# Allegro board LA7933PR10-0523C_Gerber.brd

Outline 305.85 x 179.2 mm; copper layers: TOP, GND1, IN1, VCC, IN2, IN3, GND2, IN4, GND3, BOTTOM. Coordinates in mm from the lower left corner of the outline.

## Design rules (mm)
net group CLK_CPU_DMI: nets CLK_CPU_DMI CLK_CPU_DMI#
net group CLK_CPU_ITP: nets CLK_CPU_ITP CLK_CPU_ITP#
net group CLK_PCIE_CARD: nets CLK_PCIE_CARD CLK_PCIE_CARD#
net group CLK_PCIE_EXP: nets CLK_PCIE_EXP CLK_PCIE_EXP#
net group CLK_PCIE_LAN: nets CLK_PCIE_LAN CLK_PCIE_LAN#
net group CLK_PCIE_MINI1: nets CLK_PCIE_MINI1 CLK_PCIE_MINI1#
net group CLK_PCIE_MINI2: nets CLK_PCIE_MINI2 CLK_PCIE_MINI2#
net group CLK_PCIE_MINI3: nets CLK_PCIE_MINI3 CLK_PCIE_MINI3#
net group CLK_XDP: nets CLK_XDP CLK_XDP#
net group CLK_XDP_ITP: nets CLK_XDP_ITP CLK_XDP_ITP#
net group CRT-DDC: nets CLK_DDC2_CRT DAT_DDC2_CRT
net group CSS_1: nets CSSN_1 CSSP_1
net group DDR_A_0: nets DDR_A_DQS0 DDR_A_DQS#0
net group DDR_A_1: nets DDR_A_DQS1 DDR_A_DQS#1
net group DDR_A_2: nets DDR_A_DQS2 DDR_A_DQS#2
net group DDR_A_3: nets DDR_A_DQS3 DDR_A_DQS#3
net group DDR_A_4: nets DDR_A_DQS4 DDR_A_DQS#4
net group DDR_A_5: nets DDR_A_DQS5 DDR_A_DQS#5
net group DDR_A_6: nets DDR_A_DQS6 DDR_A_DQS#6
net group DDR_A_7: nets DDR_A_DQS7 DDR_A_DQS#7
net group DDR_B_0: nets DDR_B_DQS0 DDR_B_DQS#0
net group DDR_B_1: nets DDR_B_DQS1 DDR_B_DQS#1
net group DDR_B_2: nets DDR_B_DQS2 DDR_B_DQS#2
net group DDR_B_3: nets DDR_B_DQS3 DDR_B_DQS#3
net group DDR_B_4: nets DDR_B_DQS4 DDR_B_DQS#4
net group DDR_B_5: nets DDR_B_DQS5 DDR_B_DQS#5
net group DDR_B_6: nets DDR_B_DQS6 DDR_B_DQS#6
net group DDR_B_7: nets DDR_B_DQS7 DDR_B_DQS#7
net group DIFFPAIR0: nets CARD_SMBCLK CARD_SMBDAT
net group DIFFPAIR1: nets CHARGER_SMBCLK CHARGER_SMBDAT
net group DIFFPAIR2: nets DIMM2_SMBCLK DIMM2_SMBDAT
net group DIFFPAIR3: nets DIMM1_SMBCLK DIMM1_SMBDAT
net group DIFFPAIR4: nets DIMM3_SMBCLK DIMM3_SMBDAT
net group DIFFPAIR5: nets DIMM4_SMBCLK DIMM4_SMBDAT
net group DIFFPAIR6: nets DOCK_SMB_CLK DOCK_SMB_DAT
net group DIFFPAIR7: nets DDR_XDP_WAN_SMBCLK DDR_XDP_WAN_SMBDAT
net group DIFFPAIR10: nets GPU_SMBCLK GPU_SMBDAT
net group DIFFPAIR11: nets GPU_SMBCLK_R GPU_SMBDAT_R
net group DIFFPAIR12: nets HDMI_SCL_SINK HDMI_SDA_SINK
net group DIFFPAIR13: nets SML1_SMBCLK SML1_SMBDATA
net group DIFFPAIR14: nets MEM_SMBCLK MEM_SMBDATA
net group DIFFPAIR15: nets DDR_XDP_WAN_SMBCLK_R2 DDR_XDP_WAN_SMBDAT_R2
net group DIFFPAIR16: nets LAN_SMBCLK LAN_SMBDATA
net group DIFFPAIR17: nets LAN_SMBCLK_R LAN_SMBDATA_R
net group DIFFPAIR18: nets LCD_SMBCLK LCD_SMBDAT
net group DIFFPAIR19: nets MXM_CRT_DDC_CLK MXM_CRT_DDC_DAT
net group DIFFPAIR20: nets USH_SMBCLK USH_SMBDAT
net group DIFFPAIR21: nets BAY_SMBCLK BAY_SMBDAT
net group DIFFPAIR22: nets CLK_DDC2_DOCK DAT_DDC2_DOCK
net group DIFFPAIR23: nets PCH_CRT_DDC_CLK PCH_CRT_DDC_DAT
net group DIFFPAIR24: nets USBP1_R_D+ USBP1_R_D-
net group DIFFPAIR35: nets MXM_CURI2C_CLK MXM_CURI2C_DATA
net group DMI_CRX_PTX_0: nets DMI_CRX_PTX_N0 DMI_CRX_PTX_P0
net group DMI_CRX_PTX_1: nets DMI_CRX_PTX_N1 DMI_CRX_PTX_P1
net group DMI_CRX_PTX_2: nets DMI_CRX_PTX_N2 DMI_CRX_PTX_P2
net group DMI_CRX_PTX_3: nets DMI_CRX_PTX_N3 DMI_CRX_PTX_P3
net group DMI_CTX_PRX_0: nets DMI_CTX_PRX_N0 DMI_CTX_PRX_P0
net group DMI_CTX_PRX_1: nets DMI_CTX_PRX_N1 DMI_CTX_PRX_P1
net group DMI_CTX_PRX_2: nets DMI_CTX_PRX_N2 DMI_CTX_PRX_P2
net group DMI_CTX_PRX_3: nets DMI_CTX_PRX_N3 DMI_CTX_PRX_P3
net group DOCK_DCIN_IS: nets DOCK_DCIN_IS+ DOCK_DCIN_IS-
net group DOCK_LOM_TRD0: nets DOCK_LOM_TRD0+ DOCK_LOM_TRD0-
net group DOCK_LOM_TRD1: nets DOCK_LOM_TRD1+ DOCK_LOM_TRD1-
net group DOCK_LOM_TRD2: nets DOCK_LOM_TRD2+ DOCK_LOM_TRD2-
net group DOCK_LOM_TRD3: nets DOCK_LOM_TRD3+ DOCK_LOM_TRD3-
net group DPC_DOCK_AUX: nets DPC_DOCK_AUX DPC_DOCK_AUX#
net group DPC_DOCK_SW_AUX: nets DPC_DOCK_SW_AUX DPC_DOCK_SW_AUX#
net group DPD_DOCK_AUX: nets DPD_DOCK_AUX DPD_DOCK_AUX#
net group DPD_GPU_LANE_0: nets DPD_GPU_LANE_N0 DPD_GPU_LANE_P0
net group DPD_GPU_LANE_1: nets DPD_GPU_LANE_N1 DPD_GPU_LANE_P1
net group DPD_GPU_LANE_2: nets DPD_GPU_LANE_N2 DPD_GPU_LANE_P2
net group DPD_GPU_LANE_3: nets DPD_GPU_LANE_N3 DPD_GPU_LANE_P3
net group ESATA_PRX_DTX_4_C: nets ESATA_PRX_DTX_N4_C ESATA_PRX_DTX_P4_C
net group ESATA_PTX_DRX_4_C: nets ESATA_PTX_DRX_N4_C ESATA_PTX_DRX_P4_C
net group FDI_CTX_PRX_0: nets FDI_CTX_PRX_N0 FDI_CTX_PRX_P0
net group FDI_CTX_PRX_1: nets FDI_CTX_PRX_N1 FDI_CTX_PRX_P1
net group FDI_CTX_PRX_2: nets FDI_CTX_PRX_N2 FDI_CTX_PRX_P2
net group FDI_CTX_PRX_3: nets FDI_CTX_PRX_N3 FDI_CTX_PRX_P3
net group FDI_CTX_PRX_4: nets FDI_CTX_PRX_N4 FDI_CTX_PRX_P4
net group FDI_CTX_PRX_5: nets FDI_CTX_PRX_N5 FDI_CTX_PRX_P5
net group FDI_CTX_PRX_6: nets FDI_CTX_PRX_N6 FDI_CTX_PRX_P6
net group FDI_CTX_PRX_7: nets FDI_CTX_PRX_N7 FDI_CTX_PRX_P7
net group LAN_TX0: nets LAN_TX0+ LAN_TX0-
net group LAN_TX0R: nets LAN_TX0+R LAN_TX0-R
net group LAN_TX1: nets LAN_TX1+ LAN_TX1-
net group LAN_TX1R: nets LAN_TX1+R LAN_TX1-R
net group LAN_TX2: nets LAN_TX2+ LAN_TX2-
net group LAN_TX2R: nets LAN_TX2+R LAN_TX2-R
net group LAN_TX3: nets LAN_TX3+ LAN_TX3-
net group LAN_TX3R: nets LAN_TX3+R LAN_TX3-R
net group LCD_A0_PCH: nets LCD_A0+_PCH LCD_A0-_PCH
net group LCD_A1_PCH: nets LCD_A1+_PCH LCD_A1-_PCH
net group LCD_A2_PCH: nets LCD_A2+_PCH LCD_A2-_PCH
net group LCD_ACLK_PCH: nets LCD_ACLK+_PCH LCD_ACLK-_PCH
net group LCD_B0_PCH: nets LCD_B0+_PCH LCD_B0-_PCH
net group LCD_B1_PCH: nets LCD_B1+_PCH LCD_B1-_PCH
net group LCD_B2_PCH: nets LCD_B2+_PCH LCD_B2-_PCH
net group LCD_BCLK_PCH: nets LCD_BCLK+_PCH LCD_BCLK-_PCH
net group M_CLK_DDR0: nets M_CLK_DDR0 M_CLK_DDR#0
net group M_CLK_DDR1: nets M_CLK_DDR1 M_CLK_DDR#1
net group M_CLK_DDR2: nets M_CLK_DDR2 M_CLK_DDR#2
net group M_CLK_DDR3: nets M_CLK_DDR3 M_CLK_DDR#3
net group M_CLK_DDR4: nets M_CLK_DDR4 M_CLK_DDR#4
net group M_CLK_DDR5: nets M_CLK_DDR5 M_CLK_DDR#5
net group M_CLK_DDR6: nets M_CLK_DDR6 M_CLK_DDR#6
net group M_CLK_DDR7: nets M_CLK_DDR7 M_CLK_DDR#7
net group MB_DP_RP_0: nets MB_DP_RP_N0 MB_DP_RP_P0
net group MB_DP_RP_1: nets MB_DP_RP_N1 MB_DP_RP_P1
net group MB_DP_RP_2: nets MB_DP_RP_N2 MB_DP_RP_P2
net group MB_DP_RP_3: nets MB_DP_RP_N3 MB_DP_RP_P3
net group MB_DP_RP_AUX: nets MB_DP_RP_AUX MB_DP_RP_AUX#
net group MB_DP_RP_C_0: nets MB_DP_RP_C_N0 MB_DP_RP_C_P0
net group MB_DP_RP_C_1: nets MB_DP_RP_C_N1 MB_DP_RP_C_P1
net group MB_DP_RP_C_2: nets MB_DP_RP_C_N2 MB_DP_RP_C_P2
net group MB_DP_RP_C_3: nets MB_DP_RP_C_N3 MB_DP_RP_C_P3
net group MXM_DPB_0: nets MXM_DPB_N0 MXM_DPB_P0
net group MXM_DPB_1: nets MXM_DPB_N1 MXM_DPB_P1
net group MXM_DPB_3: nets MXM_DPB_N3 MXM_DPB_P3
net group MXM_DPB_AUX: nets MXM_DPB_AUX MXM_DPB_AUX#
net group MXM_DPC_0: nets MXM_DPC_N0 MXM_DPC_P0
net group MXM_DPC_0_C: nets MXM_DPC_N0_C MXM_DPC_P0_C
net group MXM_DPC_1: nets MXM_DPC_N1 MXM_DPC_P1
net group MXM_DPC_1_C: nets MXM_DPC_N1_C MXM_DPC_P1_C
net group MXM_DPC_2: nets MXM_DPC_N2 MXM_DPC_P2
net group MXM_DPC_2_C: nets MXM_DPC_N2_C MXM_DPC_P2_C
net group MXM_DPC_3: nets MXM_DPC_N3 MXM_DPC_P3
net group MXM_DPC_3_C: nets MXM_DPC_N3_C MXM_DPC_P3_C
net group MXM_DPC_AUX: nets MXM_DPC_AUX MXM_DPC_AUX#
net group MXM_DPC_AUX_C: nets MXM_DPC_AUX#_C MXM_DPC_AUX_C
net group MXM_LVDS_A0: nets MXM_LVDS_A0+ MXM_LVDS_A0-
net group MXM_LVDS_A1: nets MXM_LVDS_A1+ MXM_LVDS_A1-
net group MXM_LVDS_A2: nets MXM_LVDS_A2+ MXM_LVDS_A2-
net group MXM_LVDS_ACLK: nets MXM_LVDS_ACLK+ MXM_LVDS_ACLK-
net group MXM_LVDS_B0: nets MXM_LVDS_B0+ MXM_LVDS_B0-
net group MXM_LVDS_B1: nets MXM_LVDS_B1+ MXM_LVDS_B1-
net group MXM_LVDS_B2: nets MXM_LVDS_B2+ MXM_LVDS_B2-
net group MXM_LVDS_BCLK: nets MXM_LVDS_BCLK+ MXM_LVDS_BCLK-
net group MXM_MB_DP_0: nets MXM_MB_DP_N0 MXM_MB_DP_P0
net group MXM_MB_DP_0_C: nets MXM_MB_DP_N0_C MXM_MB_DP_P0_C
net group MXM_MB_DP_1: nets MXM_MB_DP_N1 MXM_MB_DP_P1
net group MXM_MB_DP_1_C: nets MXM_MB_DP_N1_C MXM_MB_DP_P1_C
net group MXM_MB_DP_2: nets MXM_MB_DP_N2 MXM_MB_DP_P2
net group MXM_MB_DP_2_C: nets MXM_MB_DP_N2_C MXM_MB_DP_P2_C
net group MXM_MB_DP_3: nets MXM_MB_DP_N3 MXM_MB_DP_P3
net group MXM_MB_DP_3_C: nets MXM_MB_DP_N3_C MXM_MB_DP_P3_C
net group MXM_MB_DP_AUX: nets MXM_MB_DP_AUX MXM_MB_DP_AUX#
net group MXM_MB_DP_AUX_C: nets MXM_MB_DP_AUX#_C MXM_MB_DP_AUX_C
net group NB_LAN_TX0: nets NB_LAN_TX0+ NB_LAN_TX0-
net group NB_LAN_TX2: nets NB_LAN_TX2+ NB_LAN_TX2-
net group NB_LAN_TX3: nets NB_LAN_TX3+ NB_LAN_TX3-
net group PCIE_CARD: nets PCIE_CARD PCIE_CARD#
net group PCIE_EXP: nets PCIE_EXP PCIE_EXP#
net group PCIE_LAN: nets PCIE_LAN PCIE_LAN#
net group PCIE_MINI1: nets PCIE_MINI1 PCIE_MINI1#
net group PCIE_MINI3: nets PCIE_MINI3 PCIE_MINI3#
net group PCIE_NVR: nets PCIE_NVR PCIE_NVR#
net group PCIE_SATA_PRX_NVRTX_6: nets PCIE_SATA_PRX_NVRTX_N6 PCIE_SATA_PRX_NVRTX_P6
net group PCIE_SATA_PTX_NVRRX_6: nets PCIE_SATA_PTX_NVRRX_N6 PCIE_SATA_PTX_NVRRX_P6
net group PEG_CRX_GTX_C_0: nets PEG_CRX_GTX_C_N0 PEG_CRX_GTX_C_P0
net group PEG_CRX_GTX_C_1: nets PEG_CRX_GTX_C_N1 PEG_CRX_GTX_C_P1
net group PEG_CRX_GTX_C_2: nets PEG_CRX_GTX_C_N2 PEG_CRX_GTX_C_P2
net group PEG_CRX_GTX_C_3: nets PEG_CRX_GTX_C_N3 PEG_CRX_GTX_C_P3
net group PEG_CRX_GTX_C_4: nets PEG_CRX_GTX_C_N4 PEG_CRX_GTX_C_P4
net group PEG_CRX_GTX_C_5: nets PEG_CRX_GTX_C_N5 PEG_CRX_GTX_C_P5
net group PEG_CRX_GTX_C_6: nets PEG_CRX_GTX_C_N6 PEG_CRX_GTX_C_P6
net group PEG_CRX_GTX_C_7: nets PEG_CRX_GTX_C_N7 PEG_CRX_GTX_C_P7
net group PEG_CRX_GTX_C_8: nets PEG_CRX_GTX_C_N8 PEG_CRX_GTX_C_P8
net group PEG_CRX_GTX_C_9: nets PEG_CRX_GTX_C_N9 PEG_CRX_GTX_C_P9
net group PEG_CRX_GTX_C_10: nets PEG_CRX_GTX_C_N10 PEG_CRX_GTX_C_P10
net group PEG_CRX_GTX_C_11: nets PEG_CRX_GTX_C_N11 PEG_CRX_GTX_C_P11
net group PEG_CRX_GTX_C_12: nets PEG_CRX_GTX_C_N12 PEG_CRX_GTX_C_P12
net group PEG_CRX_GTX_C_13: nets PEG_CRX_GTX_C_N13 PEG_CRX_GTX_C_P13
net group PEG_CRX_GTX_C_14: nets PEG_CRX_GTX_C_N14 PEG_CRX_GTX_C_P14
net group PEG_CRX_GTX_C_15: nets PEG_CRX_GTX_C_N15 PEG_CRX_GTX_C_P15
net group PEG_CTX_GRX_0: nets PEG_CTX_GRX_N0 PEG_CTX_GRX_P0
net group PEG_CTX_GRX_1: nets PEG_CTX_GRX_N1 PEG_CTX_GRX_P1
net group PEG_CTX_GRX_2: nets PEG_CTX_GRX_N2 PEG_CTX_GRX_P2
net group PEG_CTX_GRX_3: nets PEG_CTX_GRX_N3 PEG_CTX_GRX_P3
net group PEG_CTX_GRX_4: nets PEG_CTX_GRX_N4 PEG_CTX_GRX_P4
net group PEG_CTX_GRX_5: nets PEG_CTX_GRX_N5 PEG_CTX_GRX_P5
net group PEG_CTX_GRX_6: nets PEG_CTX_GRX_N6 PEG_CTX_GRX_P6
net group PEG_CTX_GRX_7: nets PEG_CTX_GRX_N7 PEG_CTX_GRX_P7
net group PEG_CTX_GRX_8: nets PEG_CTX_GRX_N8 PEG_CTX_GRX_P8
net group PEG_CTX_GRX_9: nets PEG_CTX_GRX_N9 PEG_CTX_GRX_P9
net group PEG_CTX_GRX_10: nets PEG_CTX_GRX_N10 PEG_CTX_GRX_P10
net group PEG_CTX_GRX_11: nets PEG_CTX_GRX_N11 PEG_CTX_GRX_P11
net group PEG_CTX_GRX_12: nets PEG_CTX_GRX_N12 PEG_CTX_GRX_P12
net group PEG_CTX_GRX_13: nets PEG_CTX_GRX_N13 PEG_CTX_GRX_P13
net group PEG_CTX_GRX_14: nets PEG_CTX_GRX_N14 PEG_CTX_GRX_P14
net group PEG_CTX_GRX_15: nets PEG_CTX_GRX_N15 PEG_CTX_GRX_P15
net group PSATA_PRX_DTX0_RP: nets PSATA_PRX_DTX_N0_RP PSATA_PRX_DTX_P0_RP
net group PSATA_PRX_DTX_0: nets PSATA_PRX_DTX_N0 PSATA_PRX_DTX_P0
net group PSATA_PRX_DTX_0_C: nets PSATA_PRX_DTX_N0_C PSATA_PRX_DTX_P0_C
net group PSATA_PTX_DRX0_RP: nets PSATA_PTX_DRX_N0_RP PSATA_PTX_DRX_P0_RP
net group PSATA_PTX_DRX_0: nets PSATA_PTX_DRX_N0 PSATA_PTX_DRX_P0
net group PSATA_PTX_DRX_0_C: nets PSATA_PTX_DRX_N0_C PSATA_PTX_DRX_P0_C
net group REM_DIODE1__4002: nets REM_DIODE1_N_4002 REM_DIODE1_P_4002
net group REM_DIODE2__4002: nets REM_DIODE2_N_4002 REM_DIODE2_P_4002
net group REM_DIODE3__4002: nets REM_DIODE3_N_4002 REM_DIODE3_P_4002
net group REM_DIODE4__4002: nets REM_DIODE4_N_4002 REM_DIODE4_P_4002
net group REM_DIODE5__4002: nets REM_DIODE5_N_4002 REM_DIODE5_P_4002
net group SATA_NVR_PRX_DTX_2: nets SATA_NVR_PRX_DTX_N2 SATA_NVR_PRX_DTX_P2
net group SATA_NVR_PTX_DRX_2: nets SATA_NVR_PTX_DRX_N2 SATA_NVR_PTX_DRX_P2
net group SATA_NVRAM_PRX_DTX_2_C: nets SATA_NVRAM_PRX_DTX_N2_C SATA_NVRAM_PRX_DTX_P2_C
net group SATA_NVRAM_PTX_DRX_2_C: nets SATA_NVRAM_PTX_DRX_N2_C SATA_NVRAM_PTX_DRX_P2_C
net group SATA_ODD_PRX_DTX_3: nets SATA_ODD_PRX_DTX_N3 SATA_ODD_PRX_DTX_P3
net group SATA_ODD_PRX_DTX_3_C: nets SATA_ODD_PRX_DTX_N3_C SATA_ODD_PRX_DTX_P3_C
net group SATA_ODD_PTX_DRX_3: nets SATA_ODD_PTX_DRX_N3 SATA_ODD_PTX_DRX_P3
net group SATA_ODD_PTX_DRX_3_C: nets SATA_ODD_PTX_DRX_N3_C SATA_ODD_PTX_DRX_P3_C
net group SATA_PRX_DKTX_5: nets SATA_PRX_DKTX_N5 SATA_PRX_DKTX_P5
net group SATA_PRX_DKTX_5_C: nets SATA_PRX_DKTX_N5_C SATA_PRX_DKTX_P5_C
net group SATA_PRX_DTX_0: nets SATA_PRX_DTX_N0 SATA_PRX_DTX_P0
net group SATA_PRX_DTX_1: nets SATA_PRX_DTX_N1 SATA_PRX_DTX_P1
net group SATA_PRX_DTX_1_C: nets SATA_PRX_DTX_N1_C SATA_PRX_DTX_P1_C
net group SATA_PRX_DTX_4: nets SATA_PRX_DTX_N4 SATA_PRX_DTX_P4
net group SATA_PTX_DKRX_5: nets SATA_PTX_DKRX_N5 SATA_PTX_DKRX_P5
net group SATA_PTX_DKRX_5_C: nets SATA_PTX_DKRX_N5_C SATA_PTX_DKRX_P5_C
net group SATA_PTX_DRX_0: nets SATA_PTX_DRX_N0 SATA_PTX_DRX_P0
net group SATA_PTX_DRX_1: nets SATA_PTX_DRX_N1 SATA_PTX_DRX_P1
net group SATA_PTX_DRX_1_C: nets SATA_PTX_DRX_N1_C SATA_PTX_DRX_P1_C
net group SATA_PTX_DRX_4: nets SATA_PTX_DRX_N4 SATA_PTX_DRX_P4
net group SW_LAN_TX0: nets SW_LAN_TX0+ SW_LAN_TX0-
net group SW_LAN_TX1: nets SW_LAN_TX1+ SW_LAN_TX1-
net group SW_LAN_TX2: nets SW_LAN_TX2+ SW_LAN_TX2-
net group SW_LAN_TX3: nets SW_LAN_TX3+ SW_LAN_TX3-
net group SW_LVDS_A0: nets SW_LVDS_A0+ SW_LVDS_A0-
net group SW_LVDS_A1: nets SW_LVDS_A1+ SW_LVDS_A1-
net group SW_LVDS_A2: nets SW_LVDS_A2+ SW_LVDS_A2-
net group SW_LVDS_ACLK: nets SW_LVDS_ACLK+ SW_LVDS_ACLK-
net group SW_LVDS_B0: nets SW_LVDS_B0+ SW_LVDS_B0-
net group SW_LVDS_B1: nets SW_LVDS_B1+ SW_LVDS_B1-
net group SW_LVDS_B2: nets SW_LVDS_B2+ SW_LVDS_B2-
net group SW_LVDS_BCLK: nets SW_LVDS_BCLK+ SW_LVDS_BCLK-
net group TMDSE_CON_: nets TMDSE_CON_CLK TMDSE_CON_CLK#
net group TMDSE_CON_0: nets TMDSE_CON_N0 TMDSE_CON_P0
net group TMDSE_CON_1: nets TMDSE_CON_N1 TMDSE_CON_P1
net group TMDSE_CON_2: nets TMDSE_CON_N2 TMDSE_CON_P2
net group TMDSE_RP_: nets TMDSE_RP_CLK TMDSE_RP_CLK#
net group TMDSE_RP_0: nets TMDSE_RP_N0 TMDSE_RP_P0
net group TMDSE_RP_1: nets TMDSE_RP_N1 TMDSE_RP_P1
net group TMDSE_RP_2: nets TMDSE_RP_N2 TMDSE_RP_P2
net group USB3_RX1_D: nets USB3_RX1_N_D- USB3_RX1_P_D+
net group USB3_RX2D-: nets USB3_RX2_N_D- USB3_RX2_P_D+
net group USB3_TX1_D: nets USB3_TX1_N_D- USB3_TX1_P_D+
net group USB3_TX2D-: nets USB3_TX2_N_D- USB3_TX2_P_D+
net group USB3R1: nets USB3RN1 USB3RP1
net group USB3R1_C: nets USB3RN1_C USB3RP1_C
net group USB3R1_RP: nets USB3RN1_RP USB3RP1_RP
net group USB3R1_RP_R: nets USB3RN1_RP_R USB3RP1_RP_R
net group USB3R2: nets USB3RN2 USB3RP2
net group USB3R2_C: nets USB3RN2_C USB3RP2_C
net group USB3R2_RP: nets USB3RN2_RP USB3RP2_RP
net group USB3R4: nets USB3RN4 USB3RP4
net group USB3T1: nets USB3TN1 USB3TP1
net group USB3T1_C: nets USB3TN1_C USB3TP1_C
net group USB3T1_RP: nets USB3TN1_RP USB3TP1_RP
net group USB3T1_RP_C: nets USB3TN1_RP_C USB3TP1_RP_C
net group USB3T2: nets USB3TN2 USB3TP2
net group USB3T2_C: nets USB3TN2_C USB3TP2_C
net group USB3T2_RP: nets USB3TN2_RP USB3TP2_RP
net group USB3T2_RP_C: nets USB3TN2_RP_C USB3TP2_RP_C
net group USB3T4: nets USB3TN4 USB3TP4
net group USB20: nets USBP1_D+ USBP1_D-
net group USB30: nets USB3RN2_RP_R USB3RP2_RP_R
net group USBP0: nets USBP0+ USBP0-
net group USBP0_D: nets USBP0_D+ USBP0_D-
net group USBP1: nets USBP1+ USBP1-
net group USBP2: nets USBP2+ USBP2-
net group USBP3: nets USBP3+ USBP3-
net group USBP4: nets USBP4+ USBP4-
net group USBP5: nets USBP5+ USBP5-
net group USBP6: nets USBP6+ USBP6-
net group USBP7: nets USBP7+ USBP7-
net group USBP8: nets USBP8+ USBP8-
net group USBP9: nets USBP9+ USBP9-
net group USBP9_D: nets USBP9_D+ USBP9_D-
net group USBP10: nets USBP10+ USBP10-
net group USBP11: nets USBP11+ USBP11-
net group USBP12: nets USBP12+ USBP12-
net group USBP12_D: nets USBP12_D+ USBP12_D-
net group USBP13: nets USBP13+ USBP13-
net group USBP13_D: nets USBP13_D+ USBP13_D-
net group VSUM: nets VSUM+ VSUM-
net group VSUMG: nets VSUMG+ VSUMG-
net group 10: nets MAX8731_IINP
net group AC97: nets PCH_AZ_BITCLK PCH_AZ_CODEC_BITCLK PCH_AZ_CODEC_RST# PCH_AZ_CODEC_SDIN0 PCH_AZ_CODEC_SDOUT PCH_AZ_CODEC_SYNC PCH_AZ_RST# PCH_AZ_SDOUT PCH_AZ_SYNC PCH_AZ_SYNC_Q SPKR
net group CLK: nets CLK_80H CLK_PCH_14M CLK_PCI_5048 CLK_PCI_DOCK CLK_PCI_LOOPBACK CLK_PCI_MEC CLK_PCI_TPM_TCM CLK_SIO_14M EC_32KHZ_ECE5048 JETWAY_14M JETWAY_CLK14M PCH_SPI_CLK PCI_5048 PCI_DOCK PCI_LOOPBACKOUT PCI_MEC PCI_TPM_TCM PCLK_80H SIO_14M SPI_CLK32 SPI_CLK64 SPI_PCH_CLK SUSCLK
net group COMP: nets DMI_COMP_R EDP_COMP PEG_COMP SATA3_COMP SATA_COMP SM_RCOMP0 SM_RCOMP1 SM_RCOMP2 XCLK_RCOMP
net group CPU: nets DDR3_DRAMRST# DDR3_DRAMRST#_CPU DDR3_DRAMRST#_R DDR_HVREF_RST DDR_HVREF_RST_GATE DDR_HVREF_RST_PCH H_CATERR# H_CPUPWRGD H_CPUPWRGD_R H_CPUPWRGD_XDP H_PM_SYNC H_PROCHOT# H_PROCHOT#_R H_THERMTRIP# H_THERMTRIP#_R PCH_JTAG_TCK PCH_JTAG_TMS PCH_PLTRST# PCH_PLTRST#_BUF PCH_PLTRST#_EC PCH_PLTRST#_R PLTRST_GPU# PLTRST_LAN# PLTRST_MMI# PLTRST_USH# PLTRST_XDP# PM_DRAM_PWRGD PM_DRAM_PWRGD_R PROCHOT#_EC RUNPWROK THERMATRIP2# VDDPWRGOOD XDP_RST#_R XDP_TCLK
net group CRT-DAC: nets BLUE_CRT BLUE_CRT_L BLUE_DOCK GREEN_CRT GREEN_CRT_L GREEN_DOCK MXM_CRT_BLU MXM_CRT_GRN MXM_CRT_RED PCH_CRT_BLU PCH_CRT_GRN PCH_CRT_RED RED_CRT RED_CRT_L RED_DOCK
net group CRT-SYNC: nets HSYNC_BUF HSYNC_DOCK HSYNC_L MXM_CRT_HSYNC MXM_CRT_VSYNC PCH_CRT_HSYNC PCH_CRT_VSYNC VSYNC_BUF VSYNC_DOCK VSYNC_L
net group CTL-LINK: nets PCH_CL_CLK1 PCH_CL_DATA1 PCH_CL_RST1#
net group DDRA-CMD: nets DDR_A_BS0 DDR_A_BS1 DDR_A_BS2 DDR_A_CAS# DDR_A_MA0 DDR_A_MA1 DDR_A_MA2 DDR_A_MA3 DDR_A_MA4 DDR_A_MA5 DDR_A_MA6 DDR_A_MA7 DDR_A_MA8 DDR_A_MA9 DDR_A_MA10 DDR_A_MA11 DDR_A_MA12 DDR_A_MA13 DDR_A_MA14 DDR_A_MA15 DDR_A_RAS# DDR_A_WE#
net group DDRA-CTL: nets DDR_CKE0_DIMM2 DDR_CKE1_DIMM2 DDR_CKE4_DIMM1 DDR_CKE5_DIMM1 DDR_CS0_DIMM2# DDR_CS1_DIMM2# DDR_CS4_DIMM1# DDR_CS5_DIMM1# M_ODT0 M_ODT1 M_ODT4 M_ODT5
net group DDRA-D0: nets DDR_A_D0 DDR_A_D1 DDR_A_D2 DDR_A_D3 DDR_A_D4 DDR_A_D5 DDR_A_D6 DDR_A_D7
net group DDRA-D1: nets DDR_A_D8 DDR_A_D9 DDR_A_D10 DDR_A_D11 DDR_A_D12 DDR_A_D13 DDR_A_D14 DDR_A_D15
net group DDRA-D2: nets DDR_A_D16 DDR_A_D17 DDR_A_D18 DDR_A_D19 DDR_A_D20 DDR_A_D21 DDR_A_D22 DDR_A_D23
net group DDRA-D3: nets DDR_A_D24 DDR_A_D25 DDR_A_D26 DDR_A_D27 DDR_A_D28 DDR_A_D29 DDR_A_D30 DDR_A_D31
net group DDRA-D4: nets DDR_A_D32 DDR_A_D33 DDR_A_D34 DDR_A_D35 DDR_A_D36 DDR_A_D37 DDR_A_D38 DDR_A_D39
net group DDRA-D5: nets DDR_A_D40 DDR_A_D41 DDR_A_D42 DDR_A_D43 DDR_A_D44 DDR_A_D45 DDR_A_D46 DDR_A_D47
net group DDRA-D6: nets DDR_A_D48 DDR_A_D49 DDR_A_D50 DDR_A_D51 DDR_A_D52 DDR_A_D53 DDR_A_D54 DDR_A_D55
net group DDRA-D7: nets DDR_A_D56 DDR_A_D57 DDR_A_D58 DDR_A_D59 DDR_A_D60 DDR_A_D61 DDR_A_D62 DDR_A_D63
net group DDRB-CMD: nets DDR_B_BS0 DDR_B_BS1 DDR_B_BS2 DDR_B_CAS# DDR_B_MA0 DDR_B_MA1 DDR_B_MA2 DDR_B_MA3 DDR_B_MA4 DDR_B_MA5 DDR_B_MA6 DDR_B_MA7 DDR_B_MA8 DDR_B_MA9 DDR_B_MA10 DDR_B_MA11 DDR_B_MA12 DDR_B_MA13 DDR_B_MA14 DDR_B_MA15 DDR_B_RAS# DDR_B_WE#
net group DDRB-CTL: nets DDR_CKE2_DIMM4 DDR_CKE3_DIMM4 DDR_CKE6_DIMM3 DDR_CKE7_DIMM3 DDR_CS2_DIMM4# DDR_CS3_DIMM4# DDR_CS6_DIMM3# DDR_CS7_DIMM3# M_ODT2 M_ODT3 M_ODT6 M_ODT7
net group DDRB-D0: nets DDR_B_D0 DDR_B_D1 DDR_B_D2 DDR_B_D3 DDR_B_D4 DDR_B_D5 DDR_B_D6 DDR_B_D7
net group DDRB-D1: nets DDR_B_D8 DDR_B_D9 DDR_B_D10 DDR_B_D11 DDR_B_D12 DDR_B_D13 DDR_B_D14 DDR_B_D15
net group DDRB-D2: nets DDR_B_D16 DDR_B_D17 DDR_B_D18 DDR_B_D19 DDR_B_D20 DDR_B_D21 DDR_B_D22 DDR_B_D23
net group DDRB-D3: nets DDR_B_D24 DDR_B_D25 DDR_B_D26 DDR_B_D27 DDR_B_D28 DDR_B_D29 DDR_B_D30 DDR_B_D31
net group DDRB-D4: nets DDR_B_D32 DDR_B_D33 DDR_B_D34 DDR_B_D35 DDR_B_D36 DDR_B_D37 DDR_B_D38 DDR_B_D39
net group DDRB-D5: nets DDR_B_D40 DDR_B_D41 DDR_B_D42 DDR_B_D43 DDR_B_D44 DDR_B_D45 DDR_B_D46 DDR_B_D47
net group DDRB-D6: nets DDR_B_D48 DDR_B_D49 DDR_B_D50 DDR_B_D51 DDR_B_D52 DDR_B_D53 DDR_B_D54 DDR_B_D55
net group DDRB-D7: nets DDR_B_D56 DDR_B_D57 DDR_B_D58 DDR_B_D59 DDR_B_D60 DDR_B_D61 DDR_B_D62 DDR_B_D63
net group DP: nets DPC_DOCK_LANE_C_N0 DPC_DOCK_LANE_C_N1 DPC_DOCK_LANE_C_N2 DPC_DOCK_LANE_C_N3 DPC_DOCK_LANE_C_P0 DPC_DOCK_LANE_C_P1 DPC_DOCK_LANE_C_P2 DPC_DOCK_LANE_C_P3 DPC_DOCK_LANE_N0_R DPC_DOCK_LANE_N1_R DPC_DOCK_LANE_N2_R DPC_DOCK_LANE_N3_R DPC_DOCK_LANE_P0_R DPC_DOCK_LANE_P1_R DPC_DOCK_LANE_P2_R DPC_DOCK_LANE_P3_R DPD_DOCK_LANE_N0 DPD_DOCK_LANE_N0_R DPD_DOCK_LANE_N1 DPD_DOCK_LANE_N1_R DPD_DOCK_LANE_N2 DPD_DOCK_LANE_N2_R DPD_DOCK_LANE_N3 DPD_DOCK_LANE_N3_R DPD_DOCK_LANE_P0 DPD_DOCK_LANE_P0_R DPD_DOCK_LANE_P1 DPD_DOCK_LANE_P1_R DPD_DOCK_LANE_P2 DPD_DOCK_LANE_P2_R DPD_DOCK_LANE_P3 DPD_DOCK_LANE_P3_R MXM_DPB_N2 MXM_DPB_P2 MXM_DPC_HPD MXM_EDP_HPD MXM_MB_DP_HPD
net group EDP: nets MXM_EDP_AUX+ MXM_EDP_AUX+_C MXM_EDP_AUX- MXM_EDP_AUX-_C MXM_EDP_TX0+ MXM_EDP_TX0+_C MXM_EDP_TX0- MXM_EDP_TX0-_C MXM_EDP_TX1+ MXM_EDP_TX1+_C MXM_EDP_TX1- MXM_EDP_TX1-_C MXM_EDP_TX2+ MXM_EDP_TX2+_C MXM_EDP_TX2- MXM_EDP_TX2-_C MXM_EDP_TX3+ MXM_EDP_TX3+_C MXM_EDP_TX3- MXM_EDP_TX3-_C
net group FDI-CTL: nets FDI_FSYNC0 FDI_FSYNC1 FDI_INT FDI_LSYNC0 FDI_LSYNC1
net group GND: nets GND
net group HOSTCLK: nets CLK_BCLK_ITP CLK_BCLK_ITP# CLK_BUF_BCLK CLK_BUF_CKSSCD CLK_BUF_CKSSCD# CLK_BUF_DMI CLK_BUF_DMI# CLK_BUF_DOT96 CLK_BUF_DOT96# CLK_PCIE_VGA CLK_PCIE_VGA# CPU_DMI CPU_DMI# CPU_DPLL CPU_DPLL#
net group LAN: nets NB_LAN_TX0+_R NB_LAN_TX0-_R NB_LAN_TX1+ NB_LAN_TX1+_R NB_LAN_TX1- NB_LAN_TX1-_R
net group LVDS-CTL: nets LDDC_CLK_PCH LDDC_CLK_SW LDDC_DATA_PCH LDDC_DATA_SW MXM_LVDS_DDC_CLK MXM_LVDS_DDC_DAT
net group PCIE: nets PCIE_PRX_EXPTX_N3 PCIE_PRX_EXPTX_P3 PCIE_PRX_GLANTX_N7 PCIE_PRX_GLANTX_N7_C PCIE_PRX_GLANTX_P7 PCIE_PRX_GLANTX_P7_C PCIE_PRX_MMITX_N8 PCIE_PRX_MMITX_P8 PCIE_PRX_NVRTX_N6 PCIE_PRX_NVRTX_P6 PCIE_PRX_WANTX_N1 PCIE_PRX_WANTX_P1 PCIE_PRX_WLANTX_N2 PCIE_PRX_WLANTX_P2 PCIE_PRX_WPANTX_N5 PCIE_PRX_WPANTX_P5 PCIE_PTX_EXPRX_N3 PCIE_PTX_EXPRX_P3 PCIE_PTX_GLANRX_N7 PCIE_PTX_GLANRX_N7_C PCIE_PTX_GLANRX_P7 PCIE_PTX_GLANRX_P7_C PCIE_PTX_MMIRX_N8 PCIE_PTX_MMIRX_P8 PCIE_PTX_NVRRX_N6 PCIE_PTX_NVRRX_N6_C PCIE_PTX_NVRRX_P6 PCIE_PTX_NVRRX_P6_C PCIE_PTX_WANRX_N1 PCIE_PTX_WANRX_N1_C PCIE_PTX_WANRX_P1 PCIE_PTX_WANRX_P1_C PCIE_PTX_WLANRX_N2 PCIE_PTX_WLANRX_N2_C PCIE_PTX_WLANRX_P2 PCIE_PTX_WLANRX_P2_C PCIE_PTX_WPANRX_N5 PCIE_PTX_WPANRX_N5_C PCIE_PTX_WPANRX_P5 PCIE_PTX_WPANRX_P5_C
net group PEG: nets PEG_CRX_GTX_N1 PEG_CRX_GTX_N2 PEG_CRX_GTX_N3 PEG_CRX_GTX_N4 PEG_CRX_GTX_N5 PEG_CRX_GTX_N6 PEG_CRX_GTX_N7 PEG_CRX_GTX_N9 PEG_CRX_GTX_N10 PEG_CRX_GTX_N13 PEG_CRX_GTX_N15 PEG_CRX_GTX_P0 PEG_CRX_GTX_P1 PEG_CRX_GTX_P2 PEG_CRX_GTX_P3 PEG_CRX_GTX_P4 PEG_CRX_GTX_P5 PEG_CRX_GTX_P6 PEG_CRX_GTX_P7 PEG_CRX_GTX_P8 PEG_CRX_GTX_P9 PEG_CRX_GTX_P10 PEG_CRX_GTX_P11 PEG_CRX_GTX_P12 PEG_CRX_GTX_P13 PEG_CRX_GTX_P14 PEG_CRX_GTX_P15 PEG_CTX_GRX_C_N0 PEG_CTX_GRX_C_N1 PEG_CTX_GRX_C_N2 PEG_CTX_GRX_C_N3 PEG_CTX_GRX_C_N4 PEG_CTX_GRX_C_N5 PEG_CTX_GRX_C_N6 PEG_CTX_GRX_C_N7 PEG_CTX_GRX_C_N8 PEG_CTX_GRX_C_N9 PEG_CTX_GRX_C_N10 PEG_CTX_GRX_C_N11 PEG_CTX_GRX_C_N12 PEG_CTX_GRX_C_N13 PEG_CTX_GRX_C_N14 PEG_CTX_GRX_C_N15 PEG_CTX_GRX_C_P0 PEG_CTX_GRX_C_P1 PEG_CTX_GRX_C_P2 PEG_CTX_GRX_C_P3 PEG_CTX_GRX_C_P4 PEG_CTX_GRX_C_P5 PEG_CTX_GRX_C_P6 PEG_CTX_GRX_C_P7 PEG_CTX_GRX_C_P8 PEG_CTX_GRX_C_P9 PEG_CTX_GRX_C_P10 PEG_CTX_GRX_C_P11 PEG_CTX_GRX_C_P12 PEG_CTX_GRX_C_P13 PEG_CTX_GRX_C_P14 PEG_CTX_GRX_C_P15
net group PEG_CRX_GTX_0: nets PEG_CRX_GTX_N0
net group PEG_CRX_GTX_8: nets PEG_CRX_GTX_N8
net group PEG_CRX_GTX_11: nets PEG_CRX_GTX_N11
net group PEG_CRX_GTX_12: nets PEG_CRX_GTX_N12
net group PEG_CRX_GTX_14: nets PEG_CRX_GTX_N14
net group RTC: nets PCH_RTCRST# PCH_RTCX1 PCH_RTCX2 PCH_RTCX2_R SRTCRST#
net group SENSE: nets VAXG_VAL_SENSE VCC_AXG_SENSE VCCSENSE VCCSENSE_R VSS_AXG_SENSE VSSAXG_VAL_SENSE VSSSENSE VSSSENSE_R
net group SMB: nets PBAT_SMBCLK PBAT_SMBDAT WWAN_SMBCLK WWAN_SMBDAT
net group SPI: nets SPI_DIN32 SPI_DIN64 SPI_DO32 SPI_DO64 SPI_HOLD# SPI_PCH_CS0# SPI_PCH_CS0#_R SPI_PCH_CS1# SPI_PCH_CS1#_R SPI_PCH_DIN SPI_PCH_DO SPI_WP#_SEL SPI_WP#_SEL_R
net group SRCCLK: nets CLK_PCIE_NVR CLK_PCIE_NVR# PCIE_MINI2 PCIE_MINI2#
net group SVID: nets H_CPU_SVIDALRT# PECI_EC PECI_EC_R VCCSA_VID_0 VCCSA_VID_1 VIDALERT_N VIDSCLK VIDSOUT
net group UIM: nets UIM_CLK UIM_DATA UIM_RESET UIM_VPP
net group XDP: nets XDP_DBRESET# XDP_DBRESET#_R XDP_FN0 XDP_FN1 XDP_FN2 XDP_FN3 XDP_FN4 XDP_FN5 XDP_FN6 XDP_FN7 XDP_FN8 XDP_FN9 XDP_FN10 XDP_FN11 XDP_FN12 XDP_FN13 XDP_FN14 XDP_FN15 XDP_FN16 XDP_FN17 XDP_HOOK2 XDP_OBS0_R XDP_OBS1_R XDP_OBS2_R XDP_OBS3_R XDP_OBS4_R XDP_OBS5_R XDP_OBS6_R XDP_OBS7_R XDP_PRDY# XDP_PREQ# XDP_TDI XDP_TDI_R XDP_TDO XDP_TDO_R XDP_TMS XDP_TRST#
nets with their own width: min track width 0.127; nets +5V_HDMI_DDC
nets with their own width: min track width 0.203; nets MEC_XTAL1 MEC_XTAL2 MEC_XTAL2_R XTALI XTALO XTALO_R
nets with their own width: min track width 0.254; nets 1.05V_A_PWRGD 1.5V_B+ 1.5V_RUN_PWRGD 1.5V_SUS_PWRGD 1.05V_VTTPWRGD 1.5VSP_FB 1.8V_RUN_PWRGD 1.8VSP_FB 2VREF_6182 3301_ACAV_IN_NB 3301_DC_IN_SS 3301_PWRSRC +1.05V_M_VCCSUS +1.5V_RUNP +CHGR_DC_IN +VCC_GFXCORE +VCCSA_EN +VCCSA_PWRGD +VCHGR ACAV_DOCK_SRC# ACAV_IN ACAVDK_SRC ACAVIN ALW_PWRGD_3V_5V BLK_MOSFET_GC CD3301_SDC_IN CD_PBATT_OFF CPU_VTT_ON CS_1.5V CSS_GC DC_BLOCK_GC DDR_1.5V_CNTRL0 DDR_1.5V_CNTRL1 DK_AC_OFF DK_AC_OFF_EN DK_CSS_GC DK_PWR_BAR DSCHRG_MOSFET_GC EN_1.5VSP EN_1.8VSP EN_+V1.05S_VCCPP EN_+V1.05SP EN_DK_PWRBAR EN_DOCK_PWR_BAR ENTRIP1 ENTRIP2 ERC2 FB_3V FB_5V FB_+V1.05S_VCCPP FB_+V1.05SP GP1_SW GP2_SW ICOUT MAX8731_REF MOD_EN N17083694 N17319754 N21585007 N21631518 N21750145 N21752779 N22506578 N27995579 N27996731 N28024997 N28058271 N32893408 N32893413 N41278453 N41278459 N41278463 N41278649 N41343073 N47460076 N47645618 N47645638 N47645648 N47912959 N47913307 N47935277 N47935283 N47935329 N47935331 N47935380 N47935394 N47935396 N47935402 N47935438 N47935442 N47935444 N47935488 N47935534 N47935814 N47935824 N47935848 N47935871 N85751867 N85751946 N141046431 NTCG P1_SW P2_SW P3_SW P33ALW P33ALW2 P50ALW PWM3 REGCTL_PNP10 RF_+V1.05S_VCCPP RF_+V1.05SP RUN_GFX_ON RUN_GFX_ON# RUN_ON_CPU1.5VS3 S3_1.5V S5_1.5V SL_BAT_PRES# STSTART_DCBLOCK_GC TRIP_+V1.05S_VCCPP TRIP_+V1.05SP VCCP_PWRCTRL VCCSA_SENSE VCCSAPWROK VFB VSS_NCTF_1 VSS_NCTF_2 VSS_NCTF_3 VSS_NCTF_4 VSS_NCTF_5 VSS_NCTF_6 VSS_NCTF_7 VSS_NCTF_8 VSS_NCTF_9 VSS_NCTF_10 VSS_NCTF_11 VSS_NCTF_12 VSS_NCTF_13 VSS_NCTF_14 VSS_NCTF_15 VSS_NCTF_16 VSS_NCTF_17 VSS_NCTF_18 VSS_NCTF_19 VSS_NCTF_20 VSS_NCTF_21 VSS_NCTF_22 VSS_NCTF_23 VSS_NCTF_24 VSS_NCTF_25 VSS_NCTF_26 VSS_NCTF_27 VSS_NCTF_28 VSS_NCTF_29 VSS_NCTF_30 VSS_NCTF_31 VSS_NCTF_32 Z4304 Z4305 Z4306
nets with their own width: min track width 0.305; nets FFS_INT2 FFS_INT2_Q HDD_FALL_INT
nets with their own width: min track width 0.381; nets N17708032 N17708061 SOFT_START_GC
nets with their own width: min track width 0.508; nets +1.0V_LAN +1.5V_CPU_VDDQ +1.05V_M +1.5V_MEM +1.05V_RUN +1.5V_RUN +1.5V_RUN_CHG +1.05V_RUN_ENABLE +1.05V_RUN_VCCA_A_DPL +1.05V_RUN_VCCA_B_DPL +1.05V_RUN_VCCCLKDMI +1.05V_RUN_VTT +1.05VTTP +3.3V_ALW +3.3V_ALW2 +3.3V_ALW_PCH +3.3V_ALW_PCH_JTAG +3.3V_ALW_U46 +3.3V_ALWP +3.3V_ALWPCH_CHG +3.3V_LAN_OUT +3.3V_M +3.3V_M_CHG +3.3V_MXM +3.3V_RTC_LDO +3.3V_RUN +3.3V_RUN_CHG +3.3V_RUN_ENABLE +3.3V_RUN_VCC_CLKF33 +3.3V_SB3V +3.3V_SPI +3.3V_SUS +3.3V_SUS_CHG +3V_ALW_PCH_ENABLE +3VM_THRM +3VMXM_D +3VMXM_GATE +5V_ALW +5V_ALW2 +5V_ALW_ESATA +5V_ALW_PCH +5V_ALWP +5V_RUN +5V_RUN_CHG +5V_RUN_ENABLE +5VMXM_D +5VMXM_GATE +A_ENABLE +COINCELL +DC_IN +DC_IN_SS +DCIN +DDR_CHG +DIMM0_1_CA_CPU +DIMM0_1_VREF_CPU +DIMM1_VREF_DQ +DIMM3_VREF_DQ +DIMM4_VREF_CA +DIMM4_VREF_DQ +DOCK_PWR_BAR +ENAB_3VLAN +MXM_PWR_SRC +NBDOCK_DC_IN_SS +PCH_V5REF_RUN +PCH_V5REF_SUS +PECI_VREF +PWR_SRC_S +RTC_CELL +RTC_CELL_VBAT +SDC_IN +SIM_PWR +TRM_CT1 +TRM_CT2 +TRM_CT3 +TRM_CT4 +USB1_REPEATER_VDD +USB2_REPEATER_VDD +V_DDR_REF +V_DDR_REFA_M3 +V_DDR_REFB_M3 +V_DDR_SMREF +V_SM_VREF_CNT +VCC_CORE +VCC_SA +VCCACLK +VCCADAC +VCCAFDI_VRM +VCCAPLL_CPY_PCH +VCCAPLL_FDI +VCCAPLLEXP +VCCDSW3_3 +VCCSA_BT +VCCSA_BT_1 +VCCSA_P +VCCSA_SNUB +VCCSATAPLL +VCCSPI BLKNG_MOSFET_GC BOOT BOOT_1.5V BOOT_D BST_5V BST_+V1.05S_VCCPP CD3301_DCIN CHG_SNUB ERC1 ERC3 GND_CHASSIS GNDA_CHG GNDA_VCCSA MAX8731A_LDO N17684555 N21631508 N27967271 N32934056 N47912533 N47935337 N85751870 N141046260 PBATT+ SNUB_1.5V SNUB_1.5VSP SNUB_1.8VSP SNUB_+V1.05S_VCCPP SW_1.5V VDD_1.5V Z4012
nets with their own width: min track width 0.635; nets BOOT1 BOOT1G BOOT2 BOOT2G BOOT3 BST1_3V BST1_5V BST_3V PHASE2G PHASE3 SNUB_3V SNUB_5V SW_+V1.05SP UG_+V1.05SP UGATE2G UGATE3
nets with their own width: min track width 0.762; nets 1.5VSP_VIN +1.8V_RUN_LVDS +VCHGR_B CHG_LGATE CHG_UGATE LG_+V1.05S_VCCPP LG_+V1.05SP LX_5V SW_+V1.05S_VCCPP UG_5V UG_+V1.05S_VCCPP
nets with their own width: min track width 1.016; nets +0.75VSP +1.5VP +3.3V_LAN +3.3V_PCIE_NVM +3.3V_RUN_TPM +5V_RUN_CRT +5V_RUN_HDMI +CAMERA_VDD +CRT_VCC +DP_VCC +VCCDFTERM +VDISPLAY_VCC DH_1.5V DL_1.5V LG_3V LG_5V LGATE1 LGATE1G LGATE2 LGATE2G LGATE3 LX_3V PHASE2 UG_3V UGATE1 UGATE1G UGATE2
nets with their own width: min track width 2.032; nets +0.75V_DDR_VTT +1.8V_RUN +3.3V_PCIE_FLASH +3.3V_WLAN +5V_HDD +5V_USB_PWR1 +5V_USB_PWR2 +BL_PWR_SRC +DIMM2_VREF_DQ +EDPVDD +LCDVDD +PWR_SRC
nets with their own width: min track width 2.54; nets +5V_ESATA_PWR +5V_MXM
nets with their own width: min track width 3.048; nets +3.3V_PCIE_WWAN
nets with their own width: min track width 4.064; nets +5V_MOD

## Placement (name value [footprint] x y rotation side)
C1  -  [C_0603]  208.14 173.18 90 top
C2  -  [C_1206]  209.59 173.29 0 top
C3  -  [C_0603]  210.11 175.34 0 top
C4  -  [C_0402]  209.01 175.67 180 top
C7  -  [C_0402]  193.62 162.37 180 top
C8  -  [C_0402]  208.16 91.5 0 top
C12  -  [C_0402]  52.71 164.3 0 top
C13  -  [C_0402]  55.69 164.3 180 top
C14  -  [C_0402]  66.94 169.48 0 top
C15  -  [C_0402]  67.66 167.92 270 top
C18  -  [C_0402]  68.97 169.48 0 top
C19  -  [C_0402]  65.6 169.48 180 top
C20  -  [C_0402]  48.36 159.03 270 bottom
C21  -  [C_0402]  48.95 164.26 0 top
C22  -  [C_0402]  55.22 159.03 270 bottom
C23  -  [C_0402]  52.17 159.03 270 bottom
C24  -  [C_0402]  216.73 85.15 180 bottom
C45  -  [C_0402]  166.98 95.53 270 top
C48  -  [C_0402]  167.99 95.53 270 top
C52  -  [C_0402]  115.9 31.23 180 top
C53  -  [C_0402]  122.78 31.59 90 top
C56  -  [C_0402]  122.78 28.48 270 top
C86  -  [C_0402]  46.7 143.9 180 bottom
C87  -  [C_0402]  277.94 68.52 180 bottom
C88  -  [C_0402]  289.82 70.17 0 bottom
C90  -  [C_0402]  211.81 132.81 90 top
C91  -  [C_0402]  212.53 156.08 270 top
C92  -  [C_0402]  201.49 153.25 180 bottom
C93  -  [C_0402]  43.18 164.86 180 top
C94  -  [C_0402]  198.9 85.85 0 top
C95  -  [C_0402]  209.44 112.47 180 bottom
C96  -  [C_0402]  214.22 106.2 270 bottom
C242  -  [C_0402]  48.9 144.08 0 top
C243  -  [C_0402]  75.96 140.23 270 top
C244  -  [C_0402]  61.05 152.66 90 top
C245  -  [C_0402]  48.9 148.15 0 top
C246  -  [C_0402]  48.9 149.16 0 top
C247  -  [C_0402]  48.9 143.07 0 top
C248  -  [C_0402]  80.62 129.32 270 top
C249  -  [C_0603]  79.35 138.8 90 top
C250  -  [C_0603]  63.71 152.34 180 top
C251  -  [C_0402]  48.9 146.11 0 top
C252  -  [C_0402]  48.9 145.1 0 top
C253  -  [C_0402]  48.93 142.02 0 top
C254  -  [C_0402]  48.9 147.13 0 top
C255  -  [C_0402]  71.98 162.84 270 bottom
C256  -  [C_0402]  69.58 153.45 270 top
C257  -  [C_0402]  164.37 98.98 270 top
C258  -  [C_0402]  149.49 108.78 0 top
C259  -  [C_0402]  143.07 109.03 180 top
C260  -  [C_0603]  33.83 14.03 180 bottom
C272  -  [C_0402]  133.3 130.87 180 bottom
C279  -  [C_0402]  281.28 67.53 90 bottom
C280  -  [C_0402]  285.34 67.53 90 bottom
C281  -  [C_0402]  283.31 67.53 90 bottom
C282  -  [C_0402]  280.26 67.53 90 bottom
C283  -  [C_0402]  284.33 67.53 90 bottom
C284  -  [C_0402]  288.39 67.53 90 bottom
C285  -  [C_0402]  289.41 67.53 90 bottom
C286  -  [C_0402]  282.29 67.53 90 bottom
C287  -  [C_0402]  145.13 167.99 90 top
C288  -  [C_0402]  123.32 63.06 0 bottom
C289  -  [C_0402]  181.68 149.92 180 bottom
C290  -  [C_0402]  183.96 145.61 180 bottom
C292  -  [C_0402]  71.22 145.64 90 bottom
C293  -  [C_0402]  74.52 150.21 90 bottom
C294  -  [C_0402]  169.3 58.23 0 bottom
C295  -  [C_0402]  284.07 81.06 270 bottom
C296  -  [C_0603]  81.13 140.22 270 bottom
C297  -  [C_0402]  76.3 140.24 270 bottom
C298  -  [C_0402]  76.97 140.23 270 top
C299  -  [C_0402]  2.26 137 90 top
C300  -  [C_0805]  3.43 137.17 0 top
C301  -  [C_0402]  4.31 113.98 180 top
C302  -  [C_0402]  278.99 81.06 270 bottom
C303  -  [C_0402]  280.01 81.06 270 bottom
C304  -  [C_0402]  285.09 81.06 270 bottom
C305  -  [C_0402]  68.57 153.45 270 top
C306  -  [C_0402]  282.04 81.06 270 bottom
C307  -  [C_0402]  286.1 81.06 270 bottom
C308  -  [C_0402]  283.06 81.06 270 bottom
C309  -  [C_0402]  281.02 81.06 270 bottom
C310  -  [C_0402]  1.88 126.27 270 bottom
C311  -  [C_0402]  1.88 127.35 90 bottom
C313  -  [C_0402]  290.39 140.27 180 top
C323  -  [C_D2]  292.61 87.19 180 bottom
C324  -  [C_D2]  287.88 105.37 270 bottom
C327  -  [C_0402]  147.2 161.86 0 top
C328  -  [C_0603]  193.6 163.64 180 top
C329  -  [C_0805]  11.58 86.81 0 bottom
C330  -  [C_0805]  217.36 86.87 90 bottom
C332  -  [C_0603]  208.18 90.23 0 top
C333  -  [C_0402]  133.93 159.58 180 top
C334  -  [C_0402]  139.26 165.16 180 top
C335  -  [C_0402]  135.48 158.09 90 top
C336  -  [C_0402]  147.2 160.85 0 top
C337  -  [C_0402]  36.19 165.25 180 top
C338  -  [C_0805]  35.41 162.17 90 top
C339  -  [C_0402]  87.95 62.55 180 top
C340  -  [C_0402]  34.39 92.74 270 bottom
C341  -  [C_0402]  141.07 154.21 270 top
C343  -  [C_0402]  145.13 165.45 90 top
C344  -  [C_0402]  135.48 163.35 270 top
C346  -  [C_0402]  135.48 161.32 270 top
C347  -  [C_0402]  135.48 155.8 90 top
C348  -  [C_0402]  140.05 154.21 270 top
C349  -  [C_0402]  169.3 58.23 0 top
C350  -  [C_0402]  147.2 162.88 0 top
C351  -  [C_0402]  195.9 172.78 180 bottom
C352  -  [C_0603]  199.24 79.77 270 bottom
C353  -  [C_0805]  190.43 173.3 0 bottom
C354  -  [C_0402]  202.54 82.58 270 bottom
C355  -  [C_0603]  195.17 168.26 90 top
C356  -  [C_0805]  196.14 174.31 180 bottom
C357  -  [C_0805]  192.89 84.19 90 bottom
C359  -  [C_0402]  112.88 153.51 90 top
C362  -  [C_0603]  193.34 79.06 180 bottom
C364  -  [C_0402]  11.56 88.33 0 bottom
C365  -  [C_0402]  108.53 150.94 180 top
C366  -  [C_0402]  82.65 112.04 270 bottom
C367  -  [C_0402]  83.67 112.04 270 bottom
C368  -  [C_0402]  84.68 112.04 270 bottom
C369  -  [C_0402]  85.7 112.04 270 bottom
C370  -  [C_0402]  218.77 87.03 90 bottom
C371  -  [C_0402]  49.82 152.71 90 top
C372  -  [C_0402]  58.39 152.71 90 top
C373  -  [C_0402]  48.87 152.71 90 top
C374  -  [C_0402]  57.44 152.71 90 top
C375  -  [C_0402]  56.49 152.71 90 top
C376  -  [C_0402]  55.54 152.71 90 top
C377  -  [C_0402]  54.58 152.71 90 top
C378  -  [C_0402]  53.63 152.71 90 top
C379  -  [C_0402]  52.68 152.71 90 top
C380  -  [C_0402]  51.73 152.71 90 top
C383  -  [C_0402]  203.46 37.4 0 bottom
C384  -  [C_0402]  203.46 38.42 0 bottom
C385  -  [C_0402]  203.46 41.21 0 bottom
C386  -  [C_0402]  203.46 42.23 0 bottom
C387  -  [C_0402]  115.34 154.13 270 top
C388  -  [C_0402]  116.31 154.12 270 top
C389  -  [C_0402]  44.72 140.82 270 top
C390  -  [C_0402]  43.7 140.82 270 top
C391  -  [C_0402]  122.91 103.03 270 top
C392  -  [C_0603]  129.13 103.24 90 top
C393  -  [C_0603]  186.54 59.55 90 top
C394  -  [C_0805]  194.16 60.31 90 top
C395  -  [C_0402]  196.7 60.3 90 top
C397  -  [C_0402]  290.42 72.49 90 bottom
C398  -  [C_0402]  291.44 72.49 90 bottom
C402  -  [C_0402]  46.58 140.98 270 top
C403  -  [C_0402]  196.79 51.12 180 bottom
C404  -  [C_0402]  196.79 50.1 180 bottom
C405  -  [C_0402]  37.15 143.83 180 top
C406  -  [C_0402]  195.68 60.3 90 top
C407  -  [C_0402]  80.87 35.15 90 top
C408  -  [C_0402]  79.86 35.15 90 top
C409  -  [C_0402]  87.22 35.15 90 top
C410  -  [C_0402]  40.23 151.99 90 top
C411  -  [C_0402]  66.39 35.15 90 top
C412  -  [C_0402]  70.2 35.15 90 top
C413  -  [C_0402]  65.38 35.15 90 top
C414  -  [C_0402]  69.19 35.15 90 top
C415  -  [C_0402]  88.24 35.15 90 top
C416  -  [C_0603]  28.66 18.94 270 top
C417  -  [C_0805]  25.25 26.43 270 bottom
C418  -  [C_0402]  212.95 89.51 90 bottom
C419  -  [C_0402]  214.9 88.32 90 bottom
C420  -  [C_0402]  208.31 80.23 180 bottom
C421  -  [C_0402]  213.97 89.51 90 bottom
C422  -  [C_0402]  211.68 89.51 90 bottom
C423  -  [C_0402]  210.67 89.51 90 bottom
C424  -  [C_0402]  86.71 112.04 270 bottom
C425  -  [C_0402]  87.73 112.04 270 bottom
C426  -  [C_0402]  88.75 112.04 270 bottom
C427  -  [C_0402]  89.76 112.04 270 bottom
C428  -  [C_0402]  26.55 26.48 0 top
C429  -  [C_0402]  26.55 27.5 0 top
C430  -  [C_0402]  26.8 35.37 0 top
C431  -  [C_0402]  82.4 133.14 90 bottom
C432  -  [C_0402]  26.8 36.64 0 top
C433  -  [C_0402]  26.8 40.45 0 top
C434  -  [C_0402]  26.8 39.18 0 top
C435  -  [C_0402]  31.34 152.24 90 top
C436  -  [C_0402]  34.64 147.6 270 top
C437  -  [C_0402]  45.3 142.75 180 bottom
C438  -  [C_0402]  83.41 133.14 90 bottom
C439  -  [C_0402]  84.43 133.14 90 bottom
C440  -  [C_0402]  85.44 133.14 90 bottom
C441  -  [C_0402]  86.46 133.14 90 bottom
C442  -  [C_0402]  87.48 133.14 90 bottom
C443  -  [C_0402]  88.49 133.14 90 bottom
C444  -  [C_0402]  89.51 133.14 90 bottom
C445  -  [C_0402]  31.09 142.85 90 top
C446  -  [C_0402]  30.07 142.85 90 top
C447  -  [C_0402]  33.12 142.85 90 top
C448  -  [C_0402]  32.1 142.85 90 top
C449  -  [C_0805]  204.06 82.82 270 bottom
C450  -  [C_0402]  264.26 78.71 90 bottom
C451  -  [C_0402]  261.21 70.13 270 bottom
C452  -  [C_0402]  264.48 72.96 180 bottom
C453  -  [C_0402]  273.15 70.13 270 bottom
C454  -  [C_0402]  264.48 71.95 180 bottom
C455  -  [C_0402]  252.07 78.71 90 bottom
C456  -  [C_0402]  251.78 73.72 180 bottom
C457  -  [C_0402]  251.78 72.71 180 bottom
C458  -  [C_0402]  126.85 166.21 90 top
C459  -  [C_0402]  125.83 166.21 90 top
C460  -  [C_0402]  123.8 167.16 270 top
C461  -  [C_0402]  122.78 167.16 270 top
C462  -  [C_0603]  115.37 161.86 180 top
C463  -  [C_0402]  115.13 160.59 180 top
C464  -  [C_0603]  129.44 158.56 0 top
C465  -  [C_0402]  263.53 73.98 0 bottom
C466  -  [C_0402]  121.77 166.21 90 top
C467  -  [C_0402]  124.81 166.21 90 top
C468  -  [C_0402]  118.69 156.02 180 top
C469  -  [C_0402]  123.04 155.73 270 top
C470  -  [C_0402]  115.13 159.58 180 top
C471  -  [C_0402]  118.69 157.04 180 top
C472  -  [C_0402]  129.89 141.51 270 top
C473  -  [C_0402]  123.77 139.26 180 top
C474  -  [C_0402]  117.93 141.27 270 top
C475  -  [C_0603]  132.74 145.61 0 top
C476  -  [C_0402]  132.98 144.34 0 top
C477  -  [C_0402]  137.04 143.07 0 top
C478  -  [C_0402]  132.98 156.27 0 top
C479  -  [C_0603]  91.79 143.02 270 bottom
C480  -  [C_0603]  90.02 143.02 270 bottom
C481  -  [C_0603]  94.7 161.49 270 top
C482  -  [C_0805]  290.63 138.75 180 top
C483  -  [C_0402]  95.93 161.47 270 top
C484  -  [C_0603]  84.17 143.02 270 bottom
C485  -  [C_1808]  77.14 159.72 270 bottom
C486  -  [C_0603]  82.4 143.02 270 bottom
C487  -  [C_0402]  263.53 74.99 0 bottom
C488  -  [C_0402]  274.13 73.72 180 bottom
C489  -  [C_0402]  274.13 72.71 180 bottom
C490  -  [C_0402]  250.83 74.74 0 bottom
C491  -  [C_0402]  250.83 75.76 0 bottom
C492  -  [C_0402]  261.43 73.98 180 bottom
C493  -  [C_0402]  261.43 72.96 180 bottom
C496  -  [C_0402]  277.94 76.65 180 bottom
C497  -  [C_0402]  279.25 68.48 270 bottom
C498  -  [C_0805]  86.92 31.66 180 bottom
C500  -  [C_0402]  93.57 145.57 180 bottom
C501  -  [C_0402]  95 145.5 0 bottom
C502  -  [C_0402]  86.27 145.31 180 bottom
C503  -  [C_0402]  81.35 145.8 180 bottom
C550  -  [C_0402]  172.06 108.05 90 top
C551  -  [C_0402]  168.76 108.05 90 top
C552  -  [C_0402]  173.07 108.05 90 top
C553  -  [C_0402]  173.07 95.53 270 top
C554  -  [C_0402]  176.12 95.53 270 top
C593  -  [C_0402]  108.53 142.3 180 top
C594  -  [C_0402]  108.53 162.37 180 top
C595  -  [C_0402]  196.44 101.7 90 bottom
C596  -  [C_0402]  187.3 86.97 90 bottom
C597  -  [C_0402]  100.4 155.51 180 top
C598  -  [C_0402]  186.28 86.97 90 bottom
C599  -  [C_0402]  100.4 156.53 180 top
C600  -  [C_0402]  202.54 86.97 90 bottom
C601  -  [C_0402]  198.54 101.98 90 bottom
C602  -  [C_0402]  180.19 101.7 90 bottom
C603  -  [C_0402]  199.55 101.98 90 bottom
C604  -  [C_0402]  178.66 101.7 90 bottom
C605  -  [C_0402]  189.58 101.7 90 bottom
C606  -  [C_0402]  200.57 102.93 270 bottom
C607  -  [C_0402]  182.98 86.97 90 bottom
C608  -  [C_0603]  184.25 87.9 270 bottom
C609  -  [C_0402]  10.94 150.29 180 top
C610  -  [C_0402]  108.53 164.15 180 top
C611  -  [C_0402]  108.53 152.97 180 top
C612  -  [C_0402]  100.45 161.02 180 top
C613  -  [C_0805]  105.46 157.04 180 top
C614  -  [C_0402]  108.53 140.78 180 top
C615  -  [C_D2E]  94.59 133.41 180 top
C616  -  [C_0402]  263.07 31.71 0 bottom
C617  -  [C_0402]  28.5 156.1 0 top
C618  -  [C_0402]  28.5 155.05 0 top
C619  -  [C_V]  22.07 147.13 180 top
C620  -  [C_0402]  23.98 152.24 90 top
C621  -  [C_0402]  22.96 152.24 90 top
C622  -  [C_0805]  10.84 151.87 180 top
C623  -  [C_0402]  32.36 152.24 90 top
C624  -  [C_0402]  158.09 161.07 270 top
C625  -  [C_0402]  191.87 153.95 270 bottom
C626  -  [C_0402]  185.77 161.9 90 top
C628  -  [C_0402]  266.07 36.74 180 bottom
C629  -  [C_0402]  266.14 31.66 180 bottom
C630  -  [C_0402]  267.11 31.67 0 bottom
C631  -  [C_0402]  267.09 36.74 0 bottom
C632  -  [C_0402]  177.65 104.68 270 bottom
C633  -  [C_0603]  159.36 161.05 270 top
C634  -  [C_0402]  203.01 159.32 180 bottom
C635  -  [C_0402]  183.74 153.95 270 bottom
C636  -  [C_0402]  184.76 161.9 90 top
C637  -  [C_0402]  182.22 153.01 90 bottom
C638  -  [C_0402]  171.04 160.12 90 top
C639  -  [C_0402]  193.39 153.95 270 bottom
C640  -  [C_0402]  28.42 143.79 270 top
C641  -  [C_0402]  27.41 143.79 270 top
C644  -  [C_0402]  102.75 133.67 0 top
C651  -  [C_0402]  159.1 156.82 90 top
C652  -  [C_0402]  15.85 151.23 90 top
C667  -  [C_D2]  17.86 164.85 0 top
C668  -  [C_0402]  15.34 166.91 270 top
C669  -  [C_0805]  285.6 58.24 270 bottom
C670  -  [C_0402]  286.67 59.41 180 bottom
C671  -  [C_0402]  11.28 165.96 90 top
C672  -  [C_0402]  12.29 165.96 90 top
C673  -  [C_0402]  13.31 165.96 90 top
C674  -  [C_0402]  14.32 165.96 90 top
C675  -  [C_0402]  13.09 162.37 0 top
C676  -  [C_0805]  12.6 163.89 0 top
C695  -  [C_0402]  92.3 113.06 270 bottom
C696  -  [C_0402]  91.54 132.18 90 bottom
C697  -  [C_0402]  92.56 133.13 270 bottom
C698  -  [C_0402]  93.57 133.13 270 bottom
C699  -  [C_0402]  94.59 132.18 90 bottom
C700  -  [C_0402]  95.6 132.18 90 bottom
C701  -  [C_0402]  112.62 126.34 90 top
C702  -  [C_0603]  80.62 132.45 90 bottom
C703  -  [C_0603]  118.72 126.1 90 top
C704  -  [C_0402]  112.88 112.11 90 bottom
C708  -  [C_0402]  247.53 78.55 0 bottom
C709  -  [C_0402]  237.84 63.78 270 bottom
C710  -  [C_0402]  239.11 80.36 90 bottom
C711  -  [C_0402]  248.8 67.88 0 bottom
C712  -  [C_0402]  227.22 74 0 bottom
C713  -  [C_0402]  227.22 71.17 0 bottom
C714  -  [C_0603]  237.84 80.38 90 bottom
C715  -  [C_0402]  277.85 78.58 90 bottom
C716  -  [C_0402]  244.74 78.55 0 bottom
C717  -  [C_0402]  247.53 80.58 0 bottom
C718  -  [C_0402]  247.53 81.6 0 bottom
C719  -  [C_0402]  247.53 79.57 0 bottom
C720  -  [C_0402]  27.53 10.44 270 top
C721  -  [C_0402]  29.18 15.91 270 top
C722  -  [C_0402]  35.9 12.37 0 bottom
C723  -  [C_0402]  33.5 43.72 270 bottom
C724  -  [C_0402]  35.69 23.18 0 bottom
C725  -  [C_0402]  36.64 21.4 180 bottom
C726  -  [C_0402]  175.36 137.77 90 top
C727  -  [C_0402]  164.55 149.14 0 bottom
C728  -  [C_0402]  173.33 137.77 90 top
C729  -  [C_0402]  172.31 137.77 90 top
C730  -  [C_0603]  178.66 137.27 90 top
C731  -  [C_0402]  174.34 137.77 90 top
C732  -  [C_0402]  171.33 143.57 0 bottom
C733  -  [C_0402]  155.52 152.46 180 top
C734  -  [C_0402]  158.31 151.58 180 top
C735  -  [C_0402]  169.01 157.32 90 top
C736  -  [C_0402]  165.23 142.05 0 bottom
C737  -  [C_0402]  175.65 153.99 0 top
C738  -  [C_0402]  177.39 137.77 90 top
C739  -  [C_0402]  176.38 137.77 90 top
C740  -  [C_0603]  164.39 144.91 0 bottom
C741  -  [C_0402]  164.95 154.28 90 top
C742  -  [C_0402]  158.35 146.36 180 top
C743  -  [C_0402]  162.69 156.27 0 top
C744  -  [C_0402]  158.31 144.34 180 bottom
C745  -  [C_0402]  163.68 154.28 90 bottom
C746  -  [C_0402]  157.33 154.78 90 bottom
C747  -  [C_0402]  167.74 137.77 90 top
C748  -  [C_0402]  294.49 109.06 90 bottom
C749  -  [C_0402]  247.1 72.4 270 bottom
C750  -  [C_0402]  248.48 76.63 180 bottom
C753  -  [C_0402]  295.5 109.06 90 bottom
C754  -  [C_0402]  297.53 109.06 90 bottom
C756  -  [C_0402]  88.06 108.7 270 top
C757  -  [C_0402]  158.34 154.78 90 bottom
C758  -  [C_0402]  85.44 109 270 top
C759  -  [C_0402]  282.8 89.95 270 bottom
C760  -  [C_0603]  8.94 128.08 180 bottom
C761  -  [C_0402]  45.48 110.24 0 top
C762  -  [C_0402]  13.34 129.6 0 bottom
C763  -  [C_0402]  27.5 8.45 180 top
C764  -  [C_0402]  45.35 100.14 0 top
C765  -  [C_0603]  124.59 31.91 90 top
C766  -  [C_0603]  46.66 151.74 90 top
C767  -  [C_0402]  128.4 30.04 0 top
C768  -  [C_0603]  133.4 149.67 180 top
C769  -  [C_0402]  205.08 54.07 270 bottom
C770  -  [C_0402]  138.06 150.94 0 top
C771  -  [C_0805]  197.97 54.31 270 bottom
C772  -  [C_0603]  45.82 133.11 270 top
C773  -  [C_0402]  47.85 129.57 270 top
C774  -  [C_0402]  185.77 173.33 90 bottom
C775  -  [C_0805]  288.14 50.05 270 bottom
C776  -  [C_1206]  176.34 172.43 270 bottom
C777  -  [C_0402]  293.95 51.37 180 bottom
C778  -  [C_0402]  248.51 63.78 270 bottom
C787  -  [C_0402]  46.28 104.7 180 top
C788  -  [C_0402]  46.3 99.12 180 top
C793  -  [C_0603]  291.44 113.55 270 bottom
C794  -  [C_0603]  291.9 90.74 180 bottom
C1145  -  [C_0402]  76.59 135.45 0 top
C1146  -  [C_0402]  76.59 134.43 0 top
C1149  -  [C_0402]  63.89 136.72 0 top
C1159  -  [C_0402]  63.89 135.7 0 top
C1167  -  [C_0402]  78.42 163.39 270 top
C1174  -  [C_0402]  112.37 143.54 270 top
C1176  -  [C_D2E]  94.59 138.24 180 top
C1177  -  [C_0805]  115.37 165.67 180 top
C1178  -  [C_0805]  118.92 161.61 180 top
C1181  -  [C_0402]  63.57 149.56 0 bottom
C1182  -  [C_0603]  60.31 151.52 180 top
C1183  -  [C_0402]  67.54 139.21 180 top
C1184  -  [C_0402]  67.55 140.2 180 top
C1185  -  [C_0402]  63.07 140.75 270 top
C1186  -  [C_0402]  64.2 140.76 270 top
C1188  -  [C_0402]  73.51 140.11 270 top
C1332  -  [C_0402]  48.08 150.94 0 bottom
C1333  -  [C_0402]  32.95 165.68 90 top
C1334  -  [C_0402]  34.09 165.68 90 top
C1335  -  [C_0402]  32 165.68 90 top
C1336  -  [C_0402]  30.87 165.68 90 top
C1337  -  [C_0402]  29.93 165.68 90 top
C1338  -  [C_0402]  28.8 165.68 90 top
C1339  -  [C_0402]  27.67 165.68 90 top
C1340  -  [C_0402]  26.54 165.68 90 top
C1341  -  [C_0402]  290.77 61.91 180 bottom
CC1  -  [C_0402]  186.6 123.98 180 top
CC2  -  [C_0402]  186.6 126.01 180 top
CC3  -  [C_0402]  186.63 128.21 180 top
CC4  -  [C_0402]  186.63 130.37 180 top
CC5  -  [C_0402]  188.15 132.4 180 top
CC6  -  [C_0402]  188.26 134.39 180 top
CC7  -  [C_0402]  188.26 136.3 180 top
CC8  -  [C_0402]  190.06 137.73 180 top
CC9  -  [C_0402]  190.06 139.64 180 top
CC10  -  [C_0402]  188.28 141.54 180 top
CC11  -  [C_0402]  193.08 143.03 180 top
CC12  -  [C_0402]  191.18 144.93 180 top
CC13  -  [C_0402]  194.86 146.33 180 top
CC14  -  [C_0402]  192.19 148.11 180 top
CC15  -  [C_0402]  194.86 149.76 180 top
CC16  -  [C_0402]  194.86 151.79 180 top
CC17  -  [C_0402]  186.6 122.96 180 top
CC18  -  [C_0402]  186.6 124.99 180 top
CC19  -  [C_0402]  186.63 127.19 180 top
CC20  -  [C_0402]  186.63 129.35 180 top
CC21  -  [C_0402]  188.15 131.38 180 top
CC22  -  [C_0402]  188.26 133.38 180 top
CC23  -  [C_0402]  188.26 135.28 180 top
CC24  -  [C_0402]  190.06 136.72 180 top
CC25  -  [C_0402]  190.06 138.75 180 top
CC26  -  [C_0402]  188.28 140.53 180 top
CC27  -  [C_0402]  193.08 142.01 180 top
CC28  -  [C_0402]  191.18 143.92 180 top
CC29  -  [C_0402]  194.86 145.31 180 top
CC30  -  [C_0402]  192.19 147.09 180 top
CC31  -  [C_0402]  194.86 148.74 180 top
CC32  -  [C_0402]  194.86 150.77 180 top
CC33  -  [C_0402]  203.06 127.06 180 bottom
CC34  -  [C_0402]  197.81 127.95 180 bottom
CC35  -  [C_0402]  201.49 130.11 180 bottom
CC36  -  [C_0402]  201.95 133.8 180 bottom
CC37  -  [C_0402]  205.3 135.07 180 bottom
CC38  -  [C_0402]  201.95 136.21 180 bottom
CC39  -  [C_0402]  206.32 138.24 180 bottom
CC40  -  [C_0402]  201.95 139.64 180 bottom
CC41  -  [C_0402]  202.51 141.54 180 bottom
CC42  -  [C_0402]  206.32 143.07 180 bottom
CC43  -  [C_0402]  206.32 144.97 180 bottom
CC44  -  [C_0402]  206.44 147.26 180 bottom
CC45  -  [C_0402]  210.16 146.84 270 bottom
CC46  -  [C_0402]  205.49 149.29 0 bottom
CC47  -  [C_0402]  209.2 150.37 0 bottom
CC48  -  [C_0402]  209.18 152.34 0 bottom
CC49  -  [C_0402]  203.06 126.05 180 bottom
CC50  -  [C_0402]  197.81 126.94 180 bottom
CC51  -  [C_0402]  201.49 129.1 180 bottom
CC52  -  [C_0402]  201.95 132.78 180 bottom
CC53  -  [C_0402]  205.3 134.05 180 bottom
CC54  -  [C_0402]  201.95 135.19 180 bottom
CC55  -  [C_0402]  206.32 137.22 180 bottom
CC56  -  [C_0402]  201.95 138.62 180 bottom
CC57  -  [C_0402]  202.51 140.53 180 bottom
CC58  -  [C_0402]  206.32 142.05 180 bottom
CC59  -  [C_0402]  206.32 144.04 180 bottom
CC60  -  [C_0402]  206.44 146.37 180 bottom
CC61  -  [C_0402]  209.14 146.84 270 bottom
CC62  -  [C_0402]  205.49 148.27 0 bottom
CC63  -  [C_0402]  209.2 149.35 0 bottom
CC64  -  [C_0402]  209.18 151.32 0 bottom
CC65  -  [C_0402]  96.37 84.68 90 top
CC66  -  [C_0402]  76.71 93.16 0 top
CC67  -  [C_0402]  76.69 91.36 0 top
CC68  -  [C_0402]  117.45 42.45 270 top
CC69  -  [C_0402]  68.43 85.19 90 top
CC70  -  [C_0805]  114.15 61.07 90 top
CC71  -  [C_0603]  118.26 52.64 0 top
CC72  -  [C_0402]  123 59.5 180 top
CC73  -  [C_0402]  123 60.52 180 top
CC74  -  [C_0402]  123 61.53 180 top
CC75  -  [C_0603]  116.18 54.88 270 top
CC76  -  [C_0603]  114.15 54.88 270 top
CC77  -  [C_0603]  114.15 66.66 90 top
CC78  -  [C_0603]  115.92 66.66 90 top
CC79  -  [C_0603]  120.75 61.33 90 top
CC80  -  [C_0603]  119.23 61.33 90 top
CC81  -  [C_D2]  121 67.48 90 top
CC82  -  [C_0402]  117.19 67.85 270 top
CC83  -  [C_0603]  78.21 49.52 90 bottom
CC84  -  [C_0603]  76.55 49.52 90 bottom
CC85  -  [C_0603]  74.98 52.77 180 bottom
CC86  -  [C_0603]  71.6 47.13 270 bottom
CC87  -  [C_D2]  58.67 39.94 180 top
CC88  -  [C_0603]  97.18 39.94 0 bottom
CC89  -  [C_0402]  97.42 41.21 0 bottom
